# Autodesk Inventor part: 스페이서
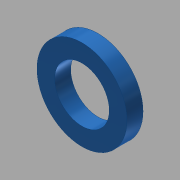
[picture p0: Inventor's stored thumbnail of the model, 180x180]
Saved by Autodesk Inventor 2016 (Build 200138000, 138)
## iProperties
Created: 2018-01
Part Number: 스페이서
Material: 스테인리스강
Document SubType Name: Modeling
Designer: mduedu
Density: 8.08 g/cm^3
Appearance: 청록색
Mass: 1.9633 g
Surface Area: 3.71101 cm^2
Volume: 0.242983 cm^3
Author: mduedu
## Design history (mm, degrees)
sketch "스케치1"
  geometry: C1 r 7 at (0, 0); C2 r 4.25 at (0, 0); 1 further point
  constraints: 2 centre point, 2 coincident
  dimensions: "d0" = 14 diameter of C1; "d1" = 8.5 diameter of C2
extrude "돌출1" new body sketch "스케치1" distance "d2" = 2.5; taper "d3" = 0 deg
node "솔리드1"
